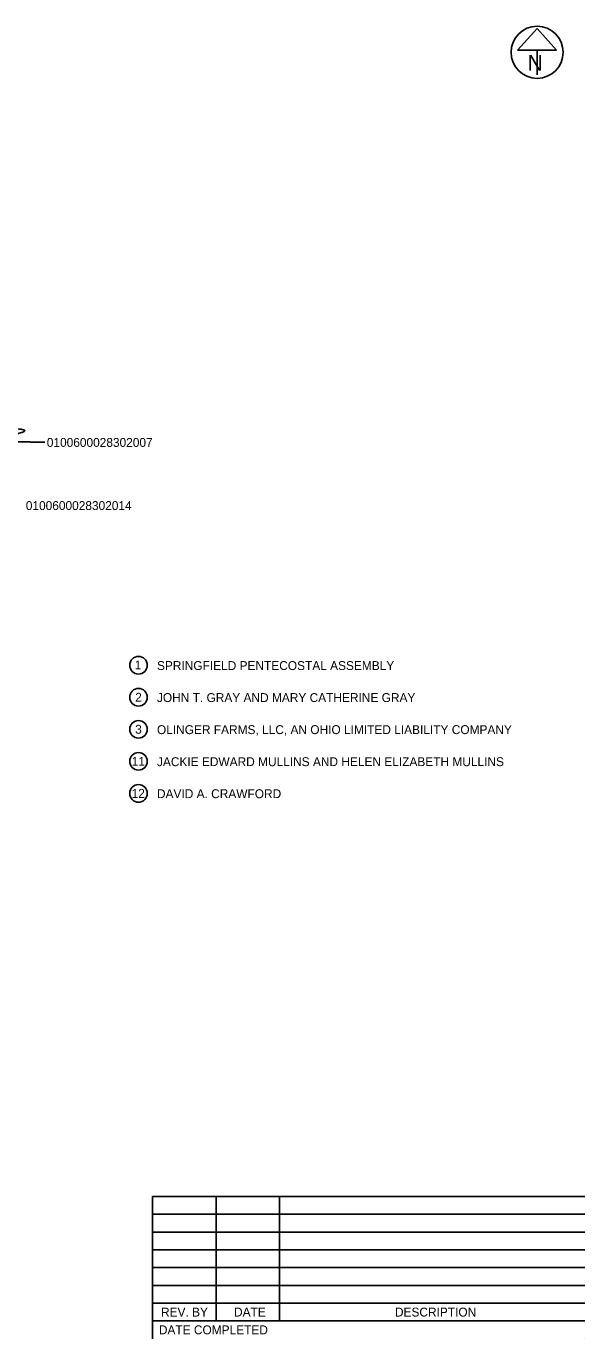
# Model space of a CAD drawing. Extents: x 1571291 to 1576333, y 700252 to 704384.
# Drawn here: x 1574575 to 1576333, y 700252 to 704384 of the extents above; entities that cross this region are included whole.
import ezdxf

# ---------------------------------------------------------------- set-up
doc = ezdxf.new("R2010")
doc.units = 0
doc.layers.add('RW_X_CL_100_Bearings', color=7, linetype='Continuous')
doc.layers.add('RW_X_CL_100_Stations', color=7, linetype='Continuous')

msp = doc.modelspace()

# ---------------------------------------------------------------- linework, layer by layer
at = {"layer": 'RW_X_CL_100_Bearings'}
for p, q in [((1576182.9, 704376.7), (1576121.3, 704308.4)), ((1576244.4, 704308.4), (1576182.9, 704376.7)), ((1576121.3, 704308.4), (1576244.4, 704308.4)), ((1576182.9, 704308.4), (1576182.9, 704231.1)), ((1574972.2, 700699.9), (1574972.2, 700251.9)), ((1574972.2, 700699.9), (1576332.9, 700699.9)), ((1575172.2, 700699.9), (1575172.2, 700307.9)), ((1575372.2, 700699.9), (1575372.2, 700307.9)), ((1574972.2, 700643.9), (1576332.9, 700643.9)), ((1574972.2, 700587.9), (1576332.9, 700587.9)), ((1574972.2, 700531.9), (1576332.9, 700531.9)), ((1574972.2, 700475.9), (1576332.9, 700475.9)), ((1574972.2, 700419.9), (1576332.9, 700419.9)), ((1574972.2, 700363.9), (1576332.9, 700363.9)), ((1574972.2, 700307.9), (1576332.9, 700307.9)), ((1576332.9, 700251.9), (1576332.9, 700251.9))]:
    msp.add_line(p, q, dxfattribs=at)
for centre, radius in [((1576182.9, 704301.9), 82), ((1574928, 702372.3), 27.7), ((1574928, 702271.4), 27.7), ((1574928, 702170.6), 27.7), ((1574928, 702069.7), 27.7), ((1574928, 701968.8), 27.7)]:
    msp.add_circle(centre, radius, dxfattribs=at)
msp.add_open_spline([(1574633.4, 703074.3), (1574608.3, 703074.3), (1574457.1, 703078.9), (1574624.6, 703119.9), (1574469.6, 703117.1)], degree=2, dxfattribs=at)
at = {"layer": 'RW_X_CL_100_Stations'}
msp.add_circle((1576182.9, 704301.9), 82, dxfattribs=at)

# ---------------------------------------------------------------- texts
at = {"layer": 'RW_X_CL_100_Bearings'}
for s, height, p in [('N', 50, (1576152.6, 704243.7)), ('0100600028302007', 28, (1574639.4, 703059.7)), ('0100600028302014', 28, (1574573.3, 702860.9)), ('1', 28, (1574916.2, 702359.1)), ('SPRINGFIELD PENTECOSTAL ASSEMBLY', 28, (1574986.2, 702357.2)), ('2', 28, (1574917.5, 702257.4)), ('JOHN T. GRAY AND MARY CATHERINE GRAY', 28, (1574986.2, 702256.4)), ('3', 28, (1574917.6, 702156.6)), ('OLINGER FARMS, LLC, AN OHIO LIMITED LIABILITY COMPANY', 28, (1574986.2, 702155.5)), ('11', 28, (1574906.8, 702055.7)), ('JACKIE EDWARD MULLINS AND HELEN ELIZABETH MULLINS', 28, (1574986.2, 702054.6)), ('12', 28, (1574906.4, 701954.8)), ('DAVID A. CRAWFORD', 28, (1574986.2, 701953.8)), ('REV. BY', 28, (1574998.9, 700321.9)), ('DATE', 28, (1575228.8, 700321.9)), ('DESCRIPTION', 28, (1575735.3, 700321.9)), ('DATE COMPLETED', 28, (1574992.2, 700265.9))]:
    msp.add_text(s, height=height, dxfattribs=at).set_placement(p)

doc.saveas('drawing.dxf')
